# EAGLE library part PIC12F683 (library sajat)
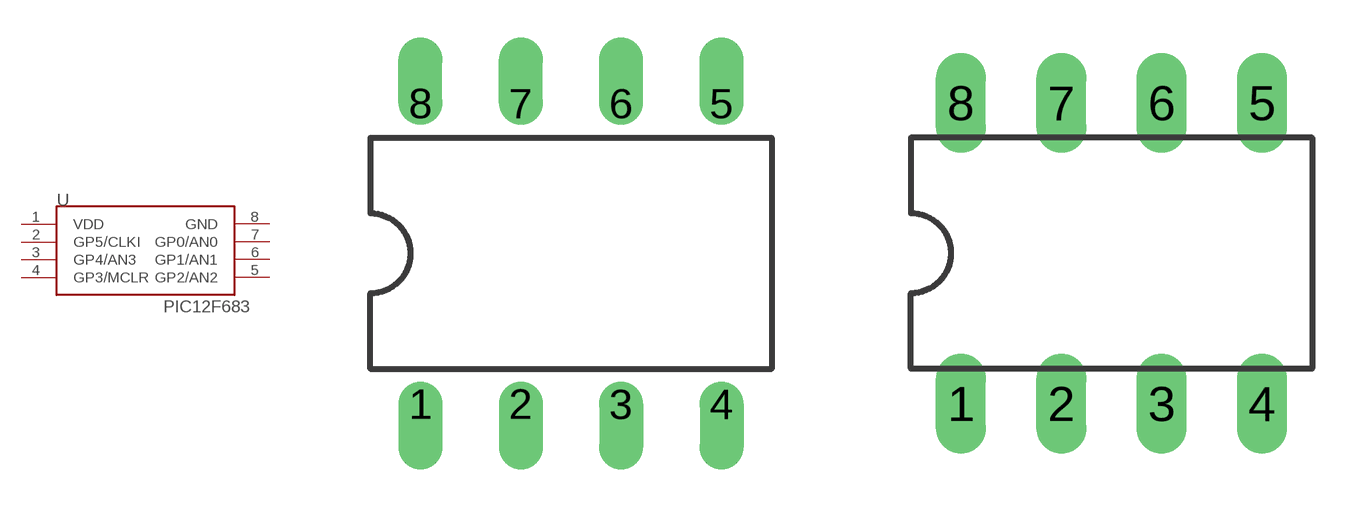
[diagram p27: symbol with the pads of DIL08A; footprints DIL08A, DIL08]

Designator prefix -

## PIC12F6831  [DIL08A]
1  VDD  pwr
2  GP5/CLKI
3  GP4/AN3
4  GP3/MCLR  in
5  GP2/AN2
6  GP1/AN1
7  GP0/AN0
8  GND  pwr

## PIC12F6832  [DIL08]
Pads as for DIL08A

## Footprint DIL08A (pad centres in mm)
Dual In Line Package
drill 0.6 pad 1.016 offset: 1 -3.81,-3.81; 2 -1.27,-3.81; 3 1.27,-3.81; 4 3.81,-3.81; 5 3.81,3.81; 6 1.27,3.81; 7 -1.27,3.81; 8 -3.81,3.81

## Footprint DIL08 (pad centres in mm)
Dual In Line Package
drill 0.5 pad 1.27 long: 1 -3.81,-3.81; 2 -1.27,-3.81; 3 1.27,-3.81; 4 3.81,-3.81; 5 3.81,3.81; 6 1.27,3.81; 7 -1.27,3.81; 8 -3.81,3.81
